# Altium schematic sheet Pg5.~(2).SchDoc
size 431 x 279 mm; Date: Not shown in title block; ApprovedBy: Not shown in title block; CheckedBy: Not shown in title block; Author: Not shown in title block; CompanyName: Not shown in title block; Engineer: Not shown in title block; Organization: Not shown in title block; Address1: Not shown in title block; Address2: Not shown in title block; Address3: Not shown in title block; Address4: Not shown in title block; DocumentNumber: 5; Revision: Use project parameter SCH_Rev; SheetNumber: 5; SheetTotal: 7; PageSetup: Record=PageOptions|CenterHorizontal=True|CenterVertical=True|PrintScale=0.59|XCorrection=1.00|YCorrection=1.00|PrintKind=0|BorderSize=5000000|LeftOffset=0|BottomOffset=0|Orientation=2|PaperLength=1000|PaperWidth=1000|Scale=100|PaperSource=15|PrintQuality=600|MediaType=1|DitherType=10|PaperKind=Letter|PrintScaleMode=1
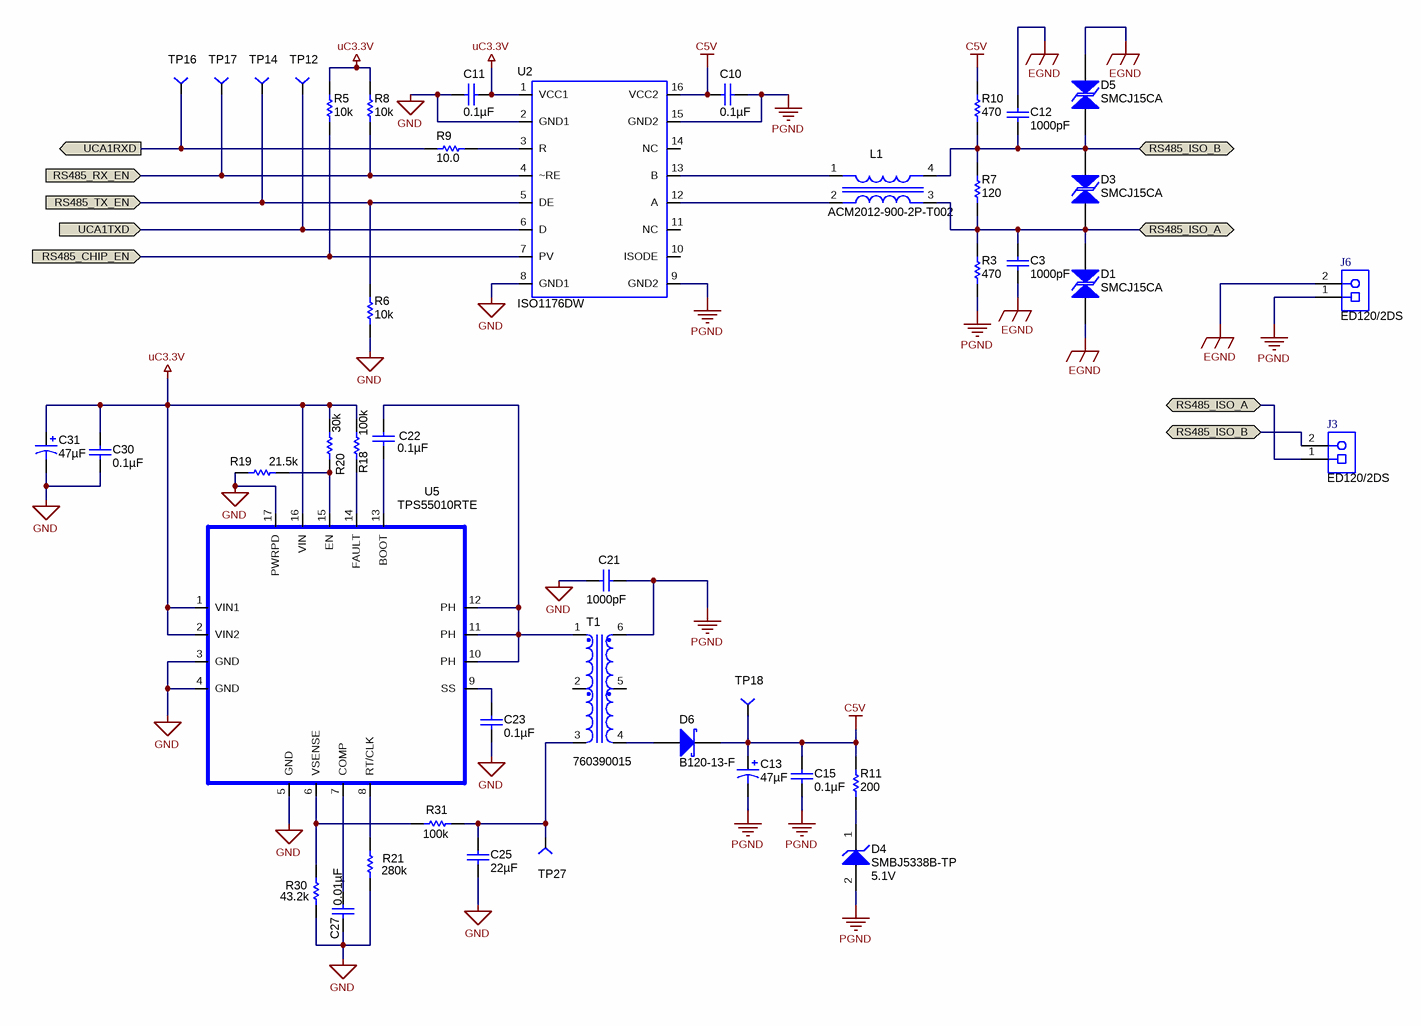
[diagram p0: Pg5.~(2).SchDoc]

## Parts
C3  ValueDisplayed: 1000pF  [1206]  (hidden comment: CC1206KKX7RCBB102)
C10  ValueDisplayed: 0.1µF  [0603]  (hidden comment: 06033C104JAT2A)
C11  ValueDisplayed: 0.1µF  [0603]  (hidden comment: 06033C104JAT2A)
C12  ValueDisplayed: 1000pF  [1206]  (hidden comment: CC1206KKX7RCBB102)
C13  ValueDisplayed: 47µF  [7343-43]  (hidden comment: T495X476K035ATE300)
C15  ValueDisplayed: 0.1µF  [0603]  (hidden comment: 06033C104JAT2A)
C21  ValueDisplayed: 1000pF  [1206]  (hidden comment: CC1206KKX7RCBB102)
C22  ValueDisplayed: 0.1µF  [0603]  (hidden comment: 06033C104JAT2A)
C23  ValueDisplayed: 0.1µF  [0603]  (hidden comment: 06033C104JAT2A)
C25  ValueDisplayed: 22µF  [1206]  (hidden comment: 1206YD226MAT2A)
C27  ValueDisplayed: 0.01µF  [0603]  (hidden comment: C1608C0G1E103J)
C30  ValueDisplayed: 0.1µF  [0603]  (hidden comment: 06033C104JAT2A)
C31  ValueDisplayed: 47µF  [7343-43]  (hidden comment: T495X476K035ATE300)
D1  SMCJ15CA  [SMC]
D3  SMCJ15CA  [SMC]
D4  SMBJ5338B-TP  value 5.1V  [SMB]
D5  SMCJ15CA  [SMC]
D6  B120-13-F  [SMA]
J3  ED120/2DS  [CONN_ED120-2DS]
J6  ED120/2DS  [CONN_ED120-2DS]
L1  ACM2012-900-2P-T002  [IND_0805-4P]
R3  value 470  [0805_HV]  (hidden comment: CRCW0805470RFKEA)
R5  value 10k  [0603]  (hidden comment: CRCW060310K0JNEA)
R6  value 10k  [0603]  (hidden comment: CRCW060310K0JNEA)
R7  value 120  [0805_HV]  (hidden comment: CRCW0805120RJNEA)
R8  value 10k  [0603]  (hidden comment: CRCW060310K0JNEA)
R9  value 10.0  [0603]  (hidden comment: CRCW060310R0FKEA)
R10  value 470  [0805_HV]  (hidden comment: CRCW0805470RFKEA)
R11  value 200  [0603]  (hidden comment: CRCW0603200RFKEA)
R18  value 100k  [0603]  (hidden comment: CRCW0603100KFKEA)
R19  value 21.5k  [0603]  (hidden comment: CRCW060321K5FKEA)
R20  value 30k  [0603]  (hidden comment: CRCW060330K0JNEA)
R21  value 280k  [0603]  (hidden comment: CRCW0603280KFKEA)
R30  value 43.2k  [0603]  (hidden comment: CRCW060343K2FKEA)
R31  value 100k  [0603]  (hidden comment: CRCW0603100KFKEA)
T1  760390015  [760390015]
TP12  TP-040_RND  [TP-040_RND]  (value not drawn)
TP14  TP-040_RND  [TP-040_RND]  (value not drawn)
TP16  TP-040_RND  [TP-040_RND]  (value not drawn)
TP17  TP-040_RND  [TP-040_RND]  (value not drawn)
TP18  TP-040_RND  [TP-040_RND]  (value not drawn)
TP27  TP-040_RND  [TP-040_RND]  (value not drawn)
U2  ISO1176DW  [DW0016A_N]
U5  TPS55010RTE  [RTE-16]

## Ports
RS485_CHIP_EN (in), RS485_ISO_A (bidir), RS485_ISO_B (bidir), RS485_RX_EN (in), RS485_TX_EN (in), UCA1RXD (out), UCA1TXD (in)

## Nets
C5V: C10.2 C13.1(+) C15.1 D6.1(K) R10.2 R11.2 TP18.1 U2.16(VCC2)
EGND: C3.2 C12.1 D1.1 D5.2 J6.2
GND: C11.1 C21.2 C23.1 C25.2 C27.2 C30.2 C31.2(-) R6.1 R19.1 R21.1 R30.1 U2.2(GND1) U2.8(GND1) U5.3(GND) U5.4(GND) U5.5(GND) U5.17(PWRPD)
PGND: C10.1 C13.2(-) C15.2 C21.1 D4.2(A) J6.1 R3.1 T1.6 U2.9(GND2) U2.15(GND2)
uC3.3V: C11.2 C30.1 C31.1(+) R5.2 R8.2 R18.2 R20.2 U2.1(VCC1) U5.1(VIN1) U5.2(VIN2) U5.16(VIN)
RS485_CHIP_EN: R5.1 U2.7(PV) ; port RS485_CHIP_EN
RS485_ISO_A: C3.1 D1.2 D3.1 J3.1 L1.3 R3.2 R7.1 ; port RS485_ISO_A
RS485_ISO_B: C12.2 D3.2 D5.1 J3.2 L1.4 R7.2 R10.1 ; port RS485_ISO_B
RS485_RX_EN: R8.1 TP17.1 U2.4(~RE) ; port RS485_RX_EN
RS485_TX_EN: R6.2 TP14.1 U2.5(DE) ; port RS485_TX_EN
UCA1RXD: R9.1 TP16.1 ; port UCA1RXD
UCA1TXD: TP12.1 U2.6(D) ; port UCA1TXD
NetC22_1: C22.1 T1.1 U5.10(PH) U5.11(PH) U5.12(PH)
NetC22_2: C22.2 U5.13(BOOT)
NetC23_2: C23.2 U5.9(SS)
NetC25_1: C25.1 R31.1 T1.3 TP27.1
NetC27_1: C27.1 U5.7(COMP)
NetD4_1: D4.1(K) R11.1
NetD6_2: D6.2(A) T1.4
NetL1_1: L1.1 U2.13(B)
NetL1_2: L1.2 U2.12(A)
NetR9_2: R9.2 U2.3(R)
NetR18_1: R18.1 U5.14(FAULT)
NetR19_2: R19.2 R20.1 U5.15(EN)
NetR21_2: R21.2 U5.8(RT/CLK)
NetR30_2: R30.2 R31.2 U5.6(VSENSE)

Not connected (* = marked no-connect by the designer): T1 2 5; U2 10(ISODE) 11(NC) 14(NC)

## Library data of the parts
C3 C12 C21 = CC1206KKX7RCBB102: CAP, CERM, 1000pF, 1000V, +/-10%, X7R, 1206; Manufacturer: Yageo America; Polarized: N; CompType: Capacitor; U/M: EA; Cap_F: 0.000000001; Tolerance_%: 10; Value1: Unknown; VDC_V: 1000; TaMin_C: -55; TaMax_C: 125
C10 C11 C15 C22 C23 C30 = 06033C104JAT2A: CAP, CERM, 0.1uF, 25V, +/-5%, X7R, 0603; Manufacturer: AVX; Polarized: N; CompType: Capacitor; U/M: EA; Cap_F: 0.0000001; Tolerance_%: 5; ESR_Ohm: 0.05; Value1: 0.05 ohm; VDC_V: 25; TaMin_C: -55; TaMax_C: 125
C13 C31 = T495X476K035ATE300: CAP, TA, 47uF, 35V, +/-10%, 0.3 ohm, SMD; Manufacturer: Kemet; Polarized: Y; CompType: Capacitor; U/M: EA; Cap_F: 0.000047; Tolerance_%: 10; Value1: 0.3 ohm; VDC_V: 35; ESR_Ohm: 0.3; IRMS_A: 0.667; TaMin_C: -55; TaMax_C: 125; Cap_Case: X
C25 = 1206YD226MAT2A: CAP, CERM, 22uF, 16V, +/-20%, X5R, 1206; Manufacturer: AVX; Polarized: N; CompType: Capacitor; U/M: EA; Cap_F: 0.000022; Tolerance_%: 20; Value1: Unknown; VDC_V: 16; TaMin_C: -55; TaMax_C: 85
C27 = C1608C0G1E103J: CAP, CERM, 0.01uF, 25V, +/-5%, C0G/NP0, 0603; Manufacturer: TDK; Polarized: N; CompType: Capacitor; U/M: EA; Cap_F: 0.00000001; Tolerance_%: 5; Value1: Unknown; VDC_V: 25; TaMin_C: -55; TaMax_C: 125
D1 D3 D5 = SMCJ15CA: Diode, TVS 15V 1500W BIDIR 5% SMC; Manufacturer: Littelfuse Inc; Power_W: 1500
D4 = SMBJ5338B-TP: Diode, Zener, 5.1V, 5W, SMB; Manufacturer: Micro Commercial Components; U/M: EA; Power_W: 5; Vz_V: 5.1; RJA_CperW: 25
D6 = B120-13-F: Diode, Schottky, 20V, 1A, SMA; Manufacturer: Diodes Inc.; U/M: EA; Vf_V: 0.5; Value2: 0.5V; Io_A: 1; Vr_V: 20; TJmax_C: 150
J3 J6 = ED120/2DS: TERMINAL BLOCK 5.08MM VERT 2POS, TH; Manufacturer: On-Shore Technology; SymbolCreator: a0412235; U/M: EA
L1 = IND_ACM2012_SERIES: Inductor, Common Mode Filter SMD; Manufacturer: TDK; Area: 8.13 mm; Value: xx uH
R3 R10 = CRCW0805470RFKEA: RES, 470 ohm, 1%, 0.125W, 0805; Manufacturer: Vishay-Dale; CompType: Resistor; Value_Code: 470R; Tolerance_%: 1; Power_W: 0.125; VDC_V: 150; TempCo: 100 ppm/C; U/M: EA
R5 R6 R8 = CRCW060310K0JNEA: RES, 10k ohm, 5%, 0.1W, 0603; Manufacturer: Vishay-Dale; CompType: Resistor; Res_ohm: 10000; Value_Code: 10k0; Tolerance_%: 5; Power_W: 0.1; VDC_V: 75; TempCo: 200 ppm/C; EIA_Code: E24; U/M: EA
R7 = CRCW0805120RJNEA: RES, 120 ohm, 5%, 0.125W, 0805; Manufacturer: Vishay-Dale; CompType: Resistor; Value_Code: 120R; Tolerance_%: 5; Power_W: 0.125; VDC_V: 150; TempCo: 200 ppm/C; EIA_Code: E24; U/M: EA
R9 = CRCW060310R0FKEA: RES, 10.0 ohm, 1%, 0.1W, 0603; Manufacturer: Vishay-Dale; CompType: Resistor; Res_ohm: 10; Value_Code: 10R0; Tolerance_%: 1; Power_W: 0.1; VDC_V: 75; TempCo: 100 ppm/C; EIA_Code: E96; U/M: EA
R11 = CRCW0603200RFKEA: RES, 200 ohm, 1%, 0.1W, 0603; Manufacturer: Vishay-Dale; CompType: Resistor; Value_Code: 200R; Tolerance_%: 1; Power_W: 0.1; VDC_V: 75; TempCo: 100 ppm/C; EIA_Code: E96; U/M: EA
R18 R31 = CRCW0603100KFKEA: RES, 100k ohm, 1%, 0.1W, 0603; Manufacturer: Vishay-Dale; CompType: Resistor; Res_ohm: 100000; Tolerance_%: 1; Power_W: 0.1; VDC_V: 75; TempCo: 100 ppm/C; EIA_Code: E96; U/M: EA
R19 = CRCW060321K5FKEA: RES, 21.5k ohm, 1%, 0.1W, 0603; Manufacturer: Vishay-Dale; CompType: Resistor; Res_ohm: 21500; Value_Code: 21k5; Tolerance_%: 1; Power_W: 0.1; VDC_V: 75; TempCo: 100 ppm/C; EIA_Code: E96; U/M: EA
R20 = CRCW060330K0JNEA: RES, 30k ohm, 5%, 0.1W, 0603; Manufacturer: Vishay-Dale; CompType: Resistor; Res_ohm: 30000; Value_Code: 30k0; Tolerance_%: 5; Power_W: 0.1; VDC_V: 75; TempCo: 200 ppm/C; EIA_Code: E24; U/M: EA
R21 = CRCW0603280KFKEA: RES, 280k ohm, 1%, 0.1W, 0603; Manufacturer: Vishay-Dale; CompType: Resistor; Res_ohm: 280000; Tolerance_%: 1; Power_W: 0.1; VDC_V: 75; TempCo: 100 ppm/C; EIA_Code: E96; U/M: EA
R30 = CRCW060343K2FKEA: RES, 43.2k ohm, 1%, 0.1W, 0603; Manufacturer: Vishay-Dale; CompType: Resistor; Res_ohm: 43200; Value_Code: 43k2; Tolerance_%: 1; Power_W: 0.1; VDC_V: 75; TempCo: 100 ppm/C; EIA_Code: E96; U/M: EA
T1 = TRNSFMR 760390015: Transformer 475uH SMD; Manufacturer: Wurth Electronics Midcom
TP12 TP14 TP16-TP18 TP27 = TP-040_RND: Test Point, O.040 Hole; Manufacturer: STD; Value: STD
U2 = ISO1176DW: IC, ISOLATED RS-485 PROFIBUS TRANSCEIVER; Manufacturer: TI; Alternate Manufacturer: None; Area: 215160
U5 = TPS55010RTE: IC, DC-DC Converter; Manufacturer: TI; Alternate Manufacturer: None; Area: 33856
